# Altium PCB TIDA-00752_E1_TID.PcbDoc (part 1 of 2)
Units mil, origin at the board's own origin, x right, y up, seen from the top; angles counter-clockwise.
Board outline 600 x 3728.74 mil, 4 copper layers (Top Layer, GND, PWR, Bottom Layer), stack 62.2 mil thick; 88 components, 42 nets, 233 pads, 115 vias.
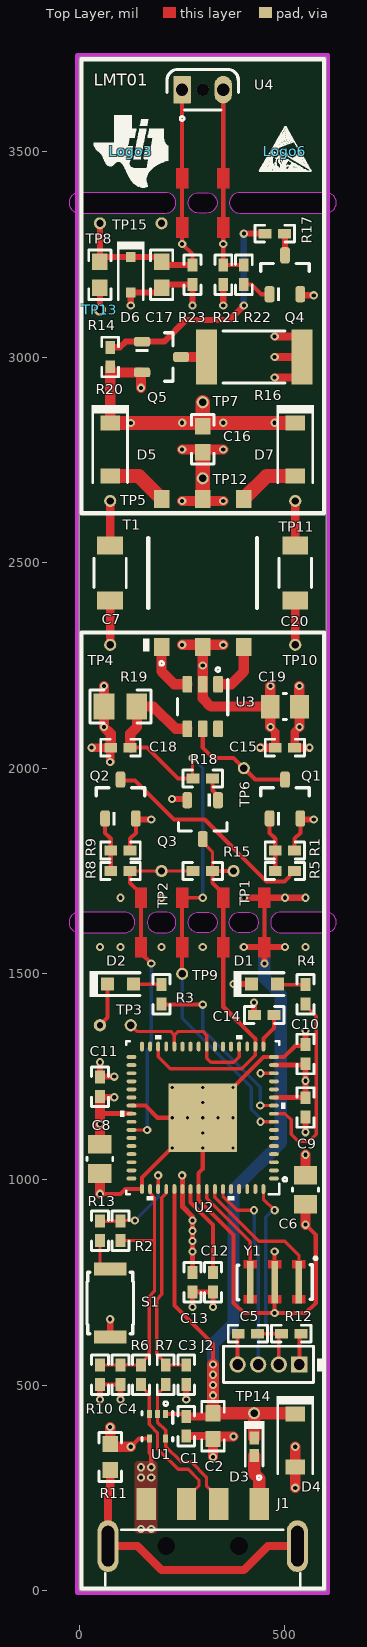
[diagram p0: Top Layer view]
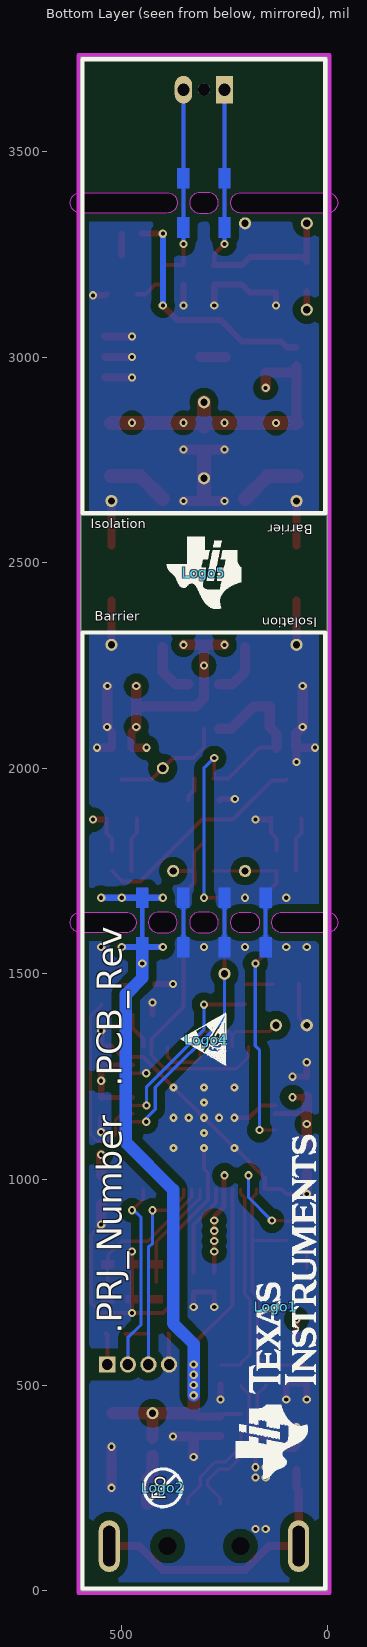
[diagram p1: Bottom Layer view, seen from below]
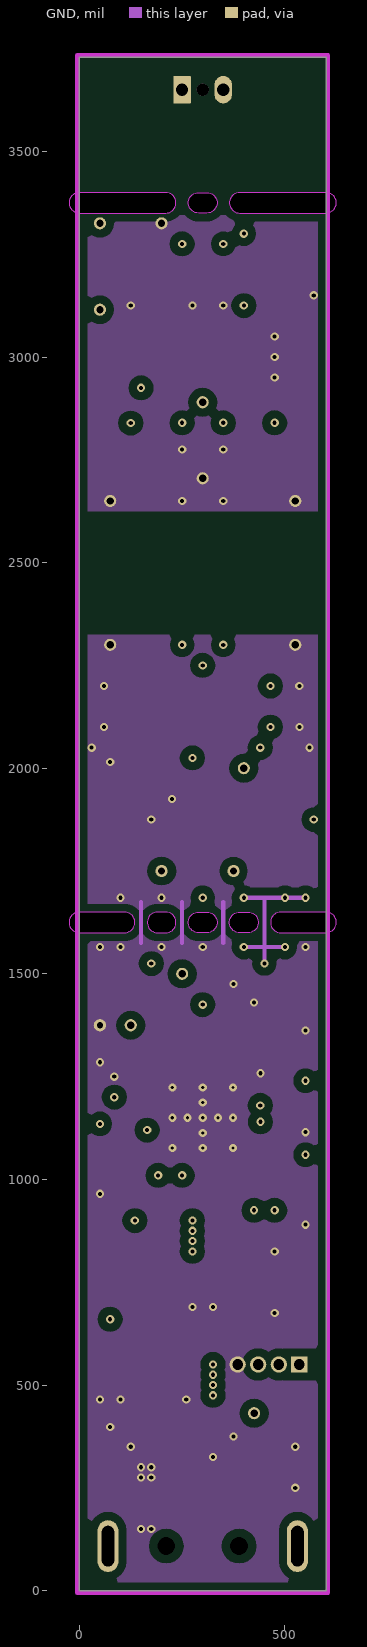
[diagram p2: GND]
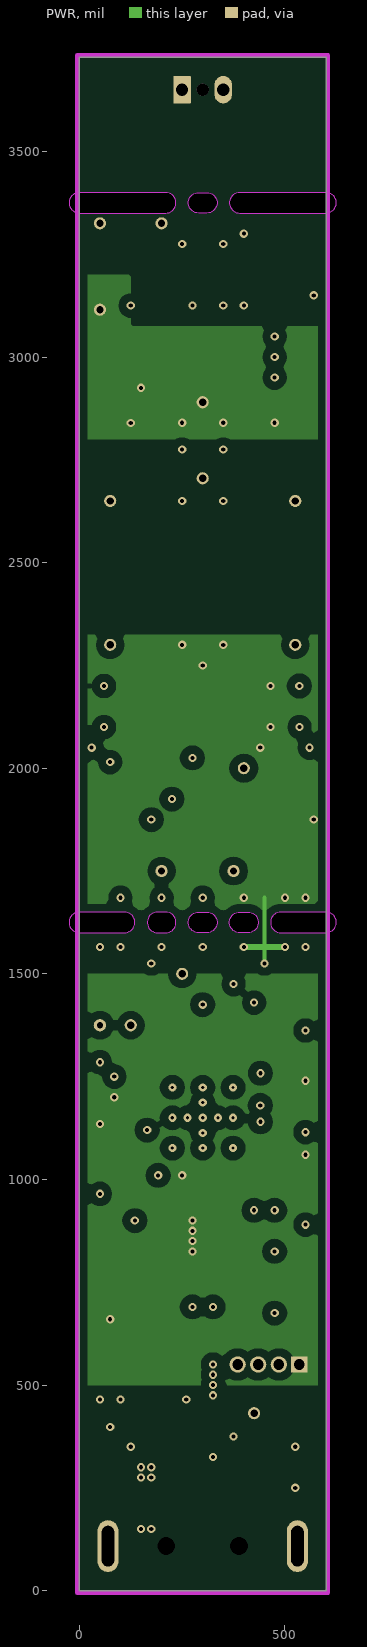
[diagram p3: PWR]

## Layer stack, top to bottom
Top Solder: solder mask 0.4, Solder Resist, Dk 3.5
Top Layer: signal copper 1.4
Dielectric 1: core 25.8, FR-4, Dk 4.2
GND: signal copper 1.4
Dielectric 2: prepreg 5, Dk 4.2
PWR: signal copper 1.4
Dielectric 3: core 25.8, FR-4, Dk 4.2
Bottom Layer: signal copper 1.4
Bottom Solder: solder mask 0.4, Solder Resist, Dk 3.5

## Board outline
0,0 0,3728.74 600,3728.74 600,0
cut-out: 0,3350 210,3350 ccw(c210,3375) 210,3400 0,3400 ccw(c0,3375)
cut-out: 290,3350 cw(c290,3375) 290,3400 310,3400 cw(c310,3375) 310,3350
cut-out: 390,3350 600,3350 ccw(c600,3375) 600,3400 390,3400 ccw(c390,3375)
cut-out: 0,1600 110,1600 ccw(c110,1625) 110,1650 0,1650 ccw(c0,1625)
cut-out: 190,1600 210,1600 ccw(c210,1625) 210,1650 190,1650 ccw(c190,1625)
cut-out: 290,1600 cw(c290,1625) 290,1650 310,1650 cw(c310,1625) 310,1600
cut-out: 390,1600 cw(c390,1625) 390,1650 410,1650 cw(c410,1625) 410,1600
cut-out: 490,1600 600,1600 ccw(c600,1625) 600,1650 490,1650 ccw(c490,1625)

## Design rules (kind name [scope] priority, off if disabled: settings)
AcuteAngle [All] p1: minimum=4.50000000000000E+0001 checktracksonly=FALSE
AssemblyTestPointUsage [All] p1: valid=2
Clearance Clearance_smd [IsSMTPin vs isvia] p1: gap=7.87
Clearance Clearance_BoardEdge_MountingHoles [OnCopper and InComponentClass('Mounting Holes') vs IsKeepOut] p2: gap=20
Clearance Clearance_BoardEdge_Poly [OnCopper and InPoly vs IsKeepOut] p3: gap=20
Clearance Clearance_BoardEdge [OnCopper and Not InComponentClass('Logo') and not InComponentClass('FiducialMark') and not InRegion(1000,500,4000,800) and Not IsKeepout vs IsKeepOut] p4: gap=20
Clearance Clearance_Poly [InPolygon] p5: gap=20
Clearance [All] p6: gap=7.87
ComponentClearance ComponentClearance_MountingHoles_FiducialMarks [InComponentClass('Mounting Holes') vs InComponentClass('FiducialMark')] p1: gap=50 collisioncheckmode=3 verticalgap=10 showdistances=FALSE
ComponentClearance ComponentClearance_Shunt [InComponentClass('Header') vs InComponentClass('Shunt')] p2: gap=0 collisioncheckmode=3 verticalgap=0 showdistances=FALSE
ComponentClearance ComponentClearance_Logo [InComponentClass('Logo')] p3: gap=50 collisioncheckmode=3 verticalgap=10 showdistances=FALSE
ComponentClearance ComponentClearance_ScrewToNut [(HasFootprint('NY PMS 440 0025 PH')) vs (HasFootprint('Keystone_1902C'))] p4: gap=5 collisioncheckmode=3 verticalgap=10 showdistances=FALSE
ComponentClearance ComponentClearance_MountingHoles [InComponentClass('Mounting Holes')] p5: gap=250 collisioncheckmode=3 verticalgap=100000 showdistances=FALSE
ComponentClearance ComponentClearance_SmallPassives [HasFootprint('0201*') or HasFootprint('0402*') or HasFootprint('0508') or HasFootprint('0603*') or HasFootprint('0612') or HasFootprint('0805*') or HasFootprint('0815*') or HasFootprint('0830*') or HasFootprint('1206*') or HasFootprint('1210*') or HasFootprint('1808*') or HasFootprint('1812*') or HasFootprint('1825*') or HasFootprint('2010*') or HasFootprint('2220*') or HasFootprint('2225*') or HasFootprint('2512*') or HasFootprint('2728*') or HasFootprint('3518*') vs HasFootprint('0201*') or HasFootprint('0402*') or HasFootprint('0508') or HasFootprint('0603*') or HasFootprint('0612') or HasFootprint('0805*') or HasFootprint('0815*') or HasFootprint('0830*') or HasFootprint('1206*') or HasFootprint('1210*') or HasFootprint('1808*') or HasFootprint('1812*') or HasFootprint('1825*') or HasFootprint('2010*') or HasFootprint('2220*') or HasFootprint('2225*') or HasFootprint('2512*') or HasFootprint('2728*') or HasFootprint('3518*')] p6: gap=15 collisioncheckmode=3 verticalgap=10 showdistances=FALSE
ComponentClearance ComponentClearance_THtoSMT [IsThruComponent vs IsSMTComponent] p7: gap=10 collisioncheckmode=3 verticalgap=30 showdistances=FALSE
ComponentClearance ComponentClearance_THtoTH [IsThruComponent vs IsThruComponent] p8: gap=30 collisioncheckmode=3 verticalgap=30 showdistances=FALSE
ComponentClearance [All] p9: gap=10 collisioncheckmode=3 verticalgap=10 showdistances=FALSE
DiffPairsRouting [All] p1: maxlimit=100 minlimit=8 mostfreqgap=10 toplayer_maxgap=15 toplayer_minwidth=8 toplayer_maxwidth=15 toplayer_prefwidth=10 midlayer1_mingap=10 midlayer1_minwidth=15 midlayer1_maxwidth=15 midlayer1_prefwidth=15 midlayer2_mingap=10 midlayer2_minwidth=15 midlayer2_maxwidth=15 midlayer2_prefwidth=15 bottomlayer_maxgap=15 bottomlayer_minwidth=8 bottomlayer_maxwidth=15 bottomlayer_prefwidth=10 maxuncoupledlength=1000
FabricationTestPointUsage TestPointUsage [All] p1: valid=2 allowmultiple=FALSE
FabricationTestpoint Testpoint [All] p1: side=3 testpointundercomponent=TRUE minsize=40 maxsize=100 preferedsize=60 minholesize=0 maxholesize=40 preferedholesize=32 testpointgrid=1 allowsidetop=TRUE allowsidebottom=TRUE usegrid=TRUE gridtolerance=0.01
FanoutControl Fanout_LCC [IsLCC] p1: bgadir=Out bgaviamode=Centered fanoutstyle=Auto fanoutdirection=Alternating viagrid=1 // Fanout_LCC (Default Rule)
FanoutControl Fanout_BGA [IsBGA] p2: bgadir=Out bgaviamode=Centered fanoutstyle=Auto fanoutdirection=Alternating viagrid=1 // Fanout_BGA (Default Rule)
FanoutControl Fanout_Default [All] p4: bgadir=Out bgaviamode=Centered fanoutstyle=Auto fanoutdirection=Alternating viagrid=1 // Fanout_Default (Default Rule)
FanoutControl Fanout_Small [(CompPinCount < 5)] p5: bgadir=Out bgaviamode=Centered fanoutstyle=Auto fanoutdirection=OutThenIn viagrid=1 // Fanout_Small (Default Rule)
HoleSize [All] p1: absolutevalues=TRUE maxlimit=251 minlimit=7.87 maxpercent=80.000 minpercent=20.000
MinimumAnnularRing MinimumAnnularRing_ThermalPadVias [IsVia and InAnyComponent] p1: minimumring=5
MinimumAnnularRing [All] p2: minimumring=5
MinimumSolderMaskSliver MinimumSolderMaskSliver_Logo [InComponentClass('Logo') vs InComponentClass('Logo')] p1: minsoldermaskwidth=0.7
MinimumSolderMaskSliver [All] p2: minsoldermaskwidth=3.94
PlaneConnect [All] p1: planeconnectstyle=Direct reliefexpansion=10 reliefentries=4 reliefconductorwidth=10 reliefairgap=10
PolygonConnect [All] p1: connectstyle=Direct reliefconductorwidth=10 reliefentries=4 polygonreliefangle="90 Angle" airgapwidth=10
RoutingVias ThermalPadVias [IsVia and InAnyComponent] p1: holewidth=7.87 width=19.68 viastyle="Through Hole" minholewidth=7.87 minwidth=19.68 maxholewidth=12.99 maxwidth=23.62
RoutingVias [All] p2: holewidth=10 width=20 viastyle="Through Hole" minholewidth=7.87 minwidth=16 maxholewidth=40 maxwidth=65
SilkToBoardRegionClearance [Not ((IsComment or IsDesignator) And (Hide <> 'False')) and not InRegion(1000,500,4000,800)] p1:
SilkToSilkClearance SilkToSilkClearance_Pb-FreeLogo [(HasFootprint('Pb-Free_Overlay_Medium') OR HasFootprint('Pb-Free_Overlay_Small')) vs (HasFootprint('Pb-Free_Overlay_Medium') OR HasFootprint('Pb-Free_Overlay_Small'))] p1: silktosilkclearance=5
SilkToSilkClearance [All] p2: silktosilkclearance=5
SilkToSolderMaskClearance SilkToComonentPadClearance [IsPad and InAnycomponent] p1: minsilkscreentomaskgap=5 clearancetoexposedcopper=TRUE
SilkToSolderMaskClearance "Silk to Solder Mask Opening" [All] p2: minsilkscreentomaskgap=5 clearancetoexposedcopper=FALSE
SolderMaskExpansion [All] p1: expansion=1.97
UnpouredPolygon [All] p1: allowunpoured=FALSE
Width [All] p1: maxlimit=100 minlimit=8 preferedwidth=10 checkconnectedcopper=TRUE
14 further rules are at their usual default settings.

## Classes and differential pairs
component class Header: J2
component class TIDA-00752_E1_MSP430_LMT01: C1 C2 C3 C4 C5 C6 C7 C8 C9 C10 C11 C12 C13 C14 C15 C16 C17 C18 C19 C20 D1 D2 D3 D4 D5 D6 D7 J1 J2 Q1 Q2 Q3 Q4 Q5 R1 R2 R3 R4 R5 R6 R7 R8 R9 R10 R11 R12 R13 R14 R15 R16 R17 R18 R19 R20 R21 R22 R23 S1 T1 TP1 TP2 TP3 TP4 TP5 TP6 TP7 TP8 TP9 TP10 TP11 TP12 TP13 TP14 TP15 U1 U2 U3 U4 Y1
component class Logo: Logo1 Logo3 Logo5
component class TIDA-00752_E1_TID_Hardware: FID1 FID2 FID3 Logo1 Logo2 Logo3 Logo4 Logo5 Logo6 ZZ1 ZZ2 ZZ3
component class AssemblyNote: ZZ1 ZZ2 ZZ3

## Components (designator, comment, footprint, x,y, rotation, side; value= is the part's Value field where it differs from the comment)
C1 "C1005X7R1H104K050BB" 0402 260,400 r270 top
C2 "0603ZD475KAT2A" 0603 325,400 r270 top
C3 "500R07S100JV4T" 0402 260,525 r270 top
C4 "500R07S100JV4T" 0402 100,525 r270 top
C5 "GRM155R70J222KA01D" 0402 410,625 r180 top
C6 "C2012X7R1A106K125AC" 0805_145 550,975 r270 top
C7 "202R18W102KV4E" 1206_190 75,2475 r270 top
C8 "C2012X7R1A106K125AC" 0805_145 50,1050 r270 top
C9 "C1005X7R1H104K050BB" 0402 550,1175 r270 top
C10 "C1005X7R1H104K050BB" 0402 550,1305 r90 top
C11 "C1005X7R1H104K050BB" 0402 50,1225 r90 top
C12 "GRM155R61A224KE19D" 0402 325,750 r270 top
C13 "GRM155R61A224KE19D" 0402 275,750 r270 top
C14 "C1005X5R1A474K050BB" 0402 450,1400 r180 top
C15 "C1005X7R1H104K050BB" 0402 500,2050 r0 top
C16 "06033C104JAT2A" 0603 300,2800 r270 top
C17 "GRM188R71A105KA61D" 0603 200,3200 r270 top
C18 "GRM155R71C224KA12D" 0402 100,2050 r180 top
C19 "EMK212BB7106MG-T" 0805_145 500,2149.99 r0 top
C20 "202R18W102KV4E" 1206_190 525,2475 r270 top
D1 "150060VS75000" WL-SMCW_GREEN 450,1475 r0 top
D2 "150060SS75000" WL-SMCW_RED 100,1475 r0 top
D3 "SBR0220T5-7-F" SOD-523 425,350 r270 top
D4 "MMSZ5232B-7-F" SOD-123 525,365 r270 top
D5 "MBR0540T1G" SOD-123 75,2775 r270 top
D6 "D3Z5V1BF-7" SOD-323F 125,3200 r270 top
D7 "MBR0540T1G" SOD-123 525,2775 r270 top
J1 "48037-2200" CONN_USB_0480372200 300,0 r0 top
J2 "850-10-004-10-001101" Preci-dip_850-xx-004-10-001101 460,550 r180 top
Logo1 "Texas Instruments" TI_Stacked_Overlay_Small 125,690 r90 bottom
Logo2 "Pb-Free Symbol" Pb-Free_Overlay_Small 400,250 r90 bottom
Logo3 "Texas Instruments" TI_Symbol_Overlay_Small 125,3500 r0 top
Logo4 "ESD Susceptible" ESD_Overlay_Small 295,1340 r90 bottom
Logo5 "Texas Instruments" TI_Symbol_Overlay_Small 300,2475 r180 bottom
Logo6 "ESD Susceptible" ESD_Overlay_Small 500,3500 r0 top
Q1 "MMBT3906" SOT-23 500,1925 r90 top
Q2 "MMBT3904" SOT-23 100,1925 r90 top
Q3 "MMBT3904" SOT-23 300,1875 r270 top
Q4 "MMBT3904" SOT-23 500,3200 r90 top
Q5 "MMBT3906" SOT-23 200,3000 r0 top
R1 "CRCW040210K0FKED" 0402 500,1800 r180 top
R2 "ERJ-2RKF1401X" 0402 100,875 r90 top
R3 "CRCW04021K00JNED" 0402 200,1450 r90 top
R4 "CRCW04021K00JNED" 0402 550,1450 r90 top
R5 "CRCW04021K00JNED" 0402 500,1750 r180 top
R6 "CRCW040227R0JNED" 0402 150,525 r90 top
R7 "CRCW040227R0JNED" 0402 210,525 r90 top
R8 "CRCW04022K00JNED" 0402 100,1750 r180 top
R9 "CRCW04021K00JNED" 0402 100,1800 r180 top
R10 "CRCW04021M00JNED" 0402 50,525 r90 top
R11 "CRCW060333R0FKEA" 0603 75,325 r270 top
R12 "CRCW040233K0JNED" 0402 515,625 r180 top
R13 "ERJ-2RKF1000X" 0402 50,875 r270 top
R14 "RC0603JR-07560RL" 0603 50,3200 r90 top
R15 "CRCW04024K70JNED" 0402 300,1750 r180 top
R16 "CRCW2512249RFKEG" 2512 425,3000 r180 top
R17 "CRCW040211K0JNED" 0402 475,3300 r180 top
R18 "CRCW040210K0FKED" 0402 300,1975 r180 top
R19 "RC0805FR-0710RL" 0805_HV 100,2150 r0 top
R20 "CRCW0402110KJNED" 0402 75,3000 r270 top
R21 "CRCW040210K0FKED" 0402 350,3200 r270 top
R22 "CRCW040222K0JNED" 0402 400,3200 r90 top
R23 "CRCW04025K10JNED" 0402 275,3200 r90 top
S1 "SKRKAEE010" SW_SKRKAEE010 75,700 r270 top
T1 "760390014" Wurth_760390013 300,2475 r90 top
TP1 "TESTPOINT" TP_H045P075 375,1750 r90 top
TP2 "TESTPOINT" TP_H045P075 200,1750 r90 top
TP3 "TESTPOINT" TP_H045P075 125,1375 r90 top
TP4 "TESTPOINT" TP_H045P075 75,2300 r90 top
TP5 "TESTPOINT" TP_H045P075 75,2650 r90 top
TP6 "TESTPOINT" TP_H045P075 400,2000 r90 top
TP7 "TESTPOINT" TP_H045P075 300,2890 r90 top
TP8 "TESTPOINT" TP_H045P075 50,3325 r90 top
TP9 "TESTPOINT" TP_H045P075 250,1500 r90 top
TP10 "TESTPOINT" TP_H045P075 525,2300 r90 top
TP11 "TESTPOINT" TP_H045P075 525,2650 r90 top
TP12 "TESTPOINT" TP_H045P075 300,2705 r90 top
TP13 "TESTPOINT" TP_H045P075 50,3115 r90 top
TP14 "TESTPOINT" TP_H045P075 425,431.5 r90 top
TP15 "TESTPOINT" TP_H045P075 200,3325 r90 top
U1 "TPD2E001DRLR" DRL0005A 190,400 r270 top
U2 "MSP430F5528IRGC" RGC0064B 300,1150 r180 top
U3 "SN6505BDBVR" DBV0006A_N 300,2150 r270 top
U4 "LMT01LPG" LPG0002A 300,3650 r0 top
Y1 "CSTCR4M00G15L99-R0" Murata_CSTCR 475,750 r180 top
ZZ1 "These assemblies are ESD sensitive, ESD precautions shall be observed." AssemblyNote 0,4975 r0 top
ZZ2 "These assemblies must be clean and free from flux and all contaminants. Use of no clean flux is not acceptable." AssemblyNote 0,4825 r0 top
ZZ3 "These assemblies must comply with workmanship standards IPC-A-610 Class 2, unless otherwise specified." AssemblyNote 0,4675 r0 top

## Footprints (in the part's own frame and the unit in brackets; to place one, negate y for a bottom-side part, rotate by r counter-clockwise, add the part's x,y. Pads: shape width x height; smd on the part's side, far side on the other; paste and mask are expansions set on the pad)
0402 [mm] "0402 from SM-752 data"
  rect 0.8x0.6 smd: 1(-0.6,0) 2(0.6,0)
  silkscreen extent -1.22,-0.52 1.22,0.52, body extent -0.55,-0.3 0.55,0.3, height 0.6
0603 [mm] "0603 from SM-752 data"
  rect 1x0.95 smd: 1(-0.8,0) 2(0.8,0)
  silkscreen extent -1.52,-0.69 1.52,0.69, body extent -0.87,-0.47 0.87,0.47, height 1
0805_145 [mm] "0805 / 1.45mm height"
  rect 1.15x1.45 smd: 1(-0.9,0) 2(0.9,0)
  silkscreen extent -0.1,-0.8 0.1,0.8, body extent -1.1,-0.72 1.1,0.72, height 1.45
0805_HV [mil] "0805 with 30mil clearance between pads"
  rect 50x63 smd: 1(-40,0) 2(40,0)
  silkscreen extent -74,-40 74,40, body extent -43,-29 43,29, height 57
1206_190 [mm] "1206_190"
  rect 1.1x1.6 smd: 1(-1.7,0) 2(1.7,0)
  silkscreen extent -0.9,-1 0.9,1, body extent -1.75,-0.95 1.75,0.95, height 1.9
2512 [mm] "Chip Resistor, Body 6.3x3.2mm, IPC Medium Density"
  rect 1.3x3.4 smd: 1(-2.95,0) 2(2.95,0)
  silkscreen extent -1.9,-1.6 1.9,1.6, body extent -3.22,-1.67 3.22,1.67, height 0.71
AssemblyNote [mil] "Assembly Note"
CONN_USB_0480372200 [mm] "MOLEX"
  rect 1.2x2 smd: 1(3.5,5.35) 2(1,5.35) 3(-1,5.35) 4(-3.5,5.35)
  oval 1.3x3.2 hole 0.762 slot 2.5 at 90 deg mask+0.064: 5(5.85,2.75) 6(-5.85,2.75)
  round 1 hole 1.1 unplated mask+0.254: 7(-2.25,2.75) 8(2.25,2.75)
  body extent -6.02,-15 6.03,5.95, height 2.25
DBV0006A_N [mm] "SOT23, 6-Leads, Body 2.9x1.6mm, Pitch 0.95mm, Lead Span 2.8mm, IPC Medium Density"
  rrect17% 1x0.6 smd: 1(-1.375,0.95) 2(-1.375,0) 3(-1.375,-0.95) 4(1.375,-0.95) 5(1.375,0) 6(1.375,0.95)
  silkscreen extent -1.68,-1.55 0.5,1.55, body extent -1.42,-1.46 1.42,1.46, height 1.12
DRL0005A [mm] "SOTFL, 5-Flat Leads, Body 1.2x1.6x0.6mm, Pitch 0.5mm, TI recommended"
  rect 0.5x0.3 smd: 1(-0.75,0.5) 2(-0.75,0) 3(-0.75,-0.5) 4(0.75,-0.5) 5(0.75,0.5)
  silkscreen extent -0.9,-0.95 0.9,0.95, body extent -0.85,-0.85 0.85,0.85, height 0.62
ESD_Overlay_Small [mil]
  silkscreen extent -62,-48 64,61
LPG0002A [mm] "TO, 2-Leads, Body 4x1.52mm"
  rrect9% 1.07x1.7 hole 0.75 mask+0.064: 1(-1.27,0)
  rrect100% 1.07x1.7 hole 0.75 mask+0.064: 2(1.27,0)
  round 0.75 hole 0.75 unplated paste+0 mask+0.127: MH(0,0)
  silkscreen extent -2.21,-1.25 2.21,1.25, body extent -2,-0.54 2,0.98, height 5.06
Murata_CSTCR [mm] "Murata"
  rect 0.4x2.6 smd mask+0.051: 1(-1.5,0) 2(0,0) 3(1.5,0)
  Top Layer region: -1.9,-1.35 -1.9,-0.85 -1.1,-0.85 -1.1,-1.35
  Top Layer region: -0.4,-1.35 -0.4,-0.85 0.4,-0.85 0.4,-1.35
  Top Layer region: -0.4,-1.35 -0.4,-0.85 0.4,-0.85 0.4,-1.35
  Top Layer region: -1.9,-1.35 -1.9,-0.85 -1.1,-0.85 -1.1,-1.35
  Top Layer region: -1.9,0.8 -1.1,0.8 -1.1,1.3 -1.9,1.3
  Top Layer region: -0.4,0.8 0.4,0.8 0.4,1.3 -0.4,1.3
  Top Layer region: 1.1,-1.35 1.1,-0.85 1.9,-0.85 1.9,-1.35
  Top Layer region: 1.1,-1.35 1.1,-0.85 1.9,-0.85 1.9,-1.35
  Top Layer region: 1.1,0.8 1.9,0.8 1.9,1.3 1.1,1.3
  silkscreen extent -2.61,-1.56 2.32,1.08, body extent -2.3,-1.05 2.3,1.05, height 1.2
Pb-Free_Overlay_Small [mil]
  silkscreen extent -46,-46 46,46
Preci-dip_850-xx-004-10-001101 [mm] "Preci-dip"
  rect 1x1 hole 0.65 mask+0.064: 1(-1.905,0)
  round 1 hole 0.65 mask+0.064: 2(-0.635,0) 3(0.635,0) 4(1.905,0)
  silkscreen extent -3.32,-1.12 2.78,1.12, body extent -2.74,-1.1 2.74,1.1, height 5.2
RGC0064B [mm]
  oval 0.6x0.24 smd mask+0.07: 1(-4.4,3.75) 2(-4.4,3.25) 3(-4.4,2.75) 4(-4.4,2.25) 5(-4.4,1.75) 6(-4.4,1.25) 7(-4.4,0.75) 8(-4.4,0.25) 9(-4.4,-0.25) 10(-4.4,-0.75) 11(-4.4,-1.25) 12(-4.4,-1.75) 13(-4.4,-2.25) 14(-4.4,-2.75) 15(-4.4,-3.25) 16(-4.4,-3.75) 33(4.4,-3.75) 34(4.4,-3.25) 35(4.4,-2.75) 36(4.4,-2.25) 37(4.4,-1.75) 38(4.4,-1.25) 39(4.4,-0.75) 40(4.4,-0.25) 41(4.4,0.25) 42(4.4,0.75) 43(4.4,1.25) 44(4.4,1.75) 45(4.4,2.25) 46(4.4,2.75) 47(4.4,3.25) 48(4.4,3.75)
  oval 0.24x0.6 smd mask+0.07: 17(-3.751,-4.4) 18(-3.251,-4.4) 19(-2.751,-4.4) 20(-2.251,-4.4) 21(-1.75,-4.4) 22(-1.25,-4.4) 23(-0.75,-4.4) 24(-0.25,-4.4) 25(0.25,-4.4) 26(0.75,-4.4) 27(1.25,-4.4) 28(1.75,-4.4) 29(2.251,-4.4) 30(2.751,-4.4) 31(3.251,-4.4) 32(3.751,-4.4) 49(3.751,4.4) 50(3.251,4.4) 51(2.751,4.4) 52(2.251,4.4) 53(1.75,4.4) 54(1.25,4.4) 55(0.75,4.4) 56(0.25,4.4) 57(-0.25,4.4) 58(-0.75,4.4) 59(-1.25,4.4) 60(-1.75,4.4) 61(-2.251,4.4) 62(-2.751,4.4) 63(-3.251,4.4) 64(-3.751,4.4)
  rect 4.25x4.25 smd paste-2.112: 65(0,0)
  silkscreen extent -5.1,-5.1 5.1,5.1, body extent -4.57,-4.57 4.57,4.57, height 1.01
SOD-123 [mm] "On Semi recommended land pattern"
  rect 0.915x1.22 smd: 1(-1.637,0) 2(1.637,0)
  silkscreen extent -2.74,-1.17 2.03,1.17, body extent -1.93,-0.9 1.93,0.9, height 1.35
SOD-323F [mm] "NXP recommended land pattern"
  rect 0.6x0.6 smd paste-0.05: 1(-1.1,0) 2(1.1,0)
  silkscreen extent -2.06,-0.86 1.53,0.86, body extent -1.35,-0.67 1.35,0.68, height 0.79
SOD-523 [mm] "NXP Semiconductor recommended land pattern, nominal STEP model"
  rect 0.8x0.6 smd paste-0.05: 1(-0.55,0) 2(0.55,0)
  silkscreen extent -1.6,-0.64 1.2,0.63, body extent -0.8,-0.4 0.8,0.4, height 0.72
SOT-23 [mm] "SOT23, 3-Leads, Body 2.9x1.3mm, Pitch 0.95mm, Lead Span 2.5mm, IPC Medium Density"
  rrect50% 1x0.6 smd: 1(-1.2,0.95) 2(-1.2,-0.95) 3(1.2,0)
  silkscreen extent -1.62,-1.5 0.7,1.5, body extent -1.16,-1.45 1.21,1.45, height 1
SW_SKRKAEE010 [mm] "Alps recommended land pattern"
  rect 0.8x2 smd: 1(-2.1,0) 2(2.1,0)
  silkscreen extent -1.9,-1.44 1.92,1.44, body extent -2.4,-1.45 2.4,1.45, height 1.96
TI_Stacked_Overlay_Small [mil]
  silkscreen extent -418,-98 418,98
TI_Symbol_Overlay_Small [mil]
  silkscreen extent -90,-88 91,88
TP_H045P075 [mm] "TP_H0.45P0.75"
  round 0.75 hole 0.45: 1(0,0)
WL-SMCW_GREEN [mm] "WURTH"
  rect 0.8x0.8 smd: 1(-0.8,0) 2(0.8,0)
  silkscreen extent -1.9,-0.8 1.2,0.8, body extent -0.85,-0.45 0.85,0.45, height 0.8
WL-SMCW_RED [mm] "WURTH"
  rect 0.8x0.8 smd: 1(-0.8,0) 2(0.8,0)
  silkscreen extent -1.9,-0.8 1.2,0.8, body extent -0.85,-0.45 0.85,0.45, height 0.8
Wurth_760390013 [mil] "Wurth"
  rect 44x38 smd: 1(-180,100) 2(-180,0) 3(-180,-100) 4(180,-100) 5(180,0) 6(180,100)
  silkscreen extent -190,-132 85,145, body extent -198,-135 198,130, height 166

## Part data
C1 C9 C10 C11 C15: "CAP, CERM, 0.1 µF, 50 V, +/- 10%, X7R, 0402"
C2: "CAP, CERM, 4.7 µF, 10 V, +/- 10%, X5R, 0603"
C3 C4: "CAP, CERM, 10 pF, 50 V, +/- 5%, C0G/NP0, 0402"
C5: "CAP, CERM, 2200pF, 6.3V, +/-10%, X7R, 0402"
C6 C8: "CAP, CERM, 10 µF, 10 V, +/- 10%, X7R, 0805"
C7 C20: "CAP, CERM, 1000 pF, 2000 V, +/- 10%, X7R, 1206_190"
C12 C13: "CAP, CERM, 0.22 µF, 10 V, +/- 10%, X5R, 0402"
C14: "CAP, CERM, 0.47 µF, 10 V, +/- 10%, X5R, 0402"
C16: "CAP, CERM, 0.1 µF, 25 V, +/- 5%, X7R, 0603"
C17: "CAP, CERM, 1 µF, 10 V, +/- 10%, X7R, 0603"
C18: "CAP, CERM, 0.22 µF, 16 V, +/- 10%, X7R, 0402"
C19: "CAP, CERM, 10 µF, 16 V, +/- 20%, X7R, 0805"
D1: "LED, Green, SMD"
D2: "LED, Super Red, SMD"
D3: "Diode, Schottky, 20 V, 0.2 A, SOD-523"
D4: "Diode, Zener, 5.6V, 500mW, SOD-123"
D5 D7: "Diode, Schottky, 40 V, 0.5 A, SOD-123"
D6: "Diode, Zener, 5.1 V, 400 mW, SOD-323F"
J1: "Connector, Plug, USB Type A, R/A, Top Mount SMT"
J2: "Header, 50mil, 4x1, Gold, TH"
Logo1 Logo3 Logo5: library part TI_Logo, "Texas Instrument Corporate Signature"
Logo2: library part Pb-Free
Logo4 Logo6: library part ESD_Susceptible, "ESD Susceptible Symbol"
Q1 Q5: library part "MMBT3906, Fairchild Semiconductor", "Transistor, PNP, 40 V, 0.2 A, SOT-23"
Q2 Q3 Q4: library part "MMBT3904, Fairchild Semiconductor", "Transistor, NPN, 40 V, 0.2 A, SOT-23"
R1 R18 R21: "RES, 10.0 k, 1%, 0.063 W, 0402"
R2: "RES, 1.40 k, 1%, 0.1 W, 0402"
R3 R4: "RES, 1.0k ohm, 5%, 0.063W, 0402"
R5 R9: "RES, 1.0 k, 5%, 0.063 W, 0402"
R6 R7: "RES, 27, 5%, 0.063 W, 0402"
R8: "RES, 2.0 k, 5%, 0.063 W, 0402"
R10: library part CRCW040233K0JNED, "RES,1M ohm, 5%, 0.063W, 0402"
R11: "RES, 33.0, 1%, 0.1 W, 0603"
R12: "RES, 33k ohm, 5%, 0.063W, 0402"
R13: "RES, 100, 1%, 0.1 W, 0402"
R14: "RES, 560, 5%, 0.1 W, 0603"
R15: "RES, 4.7 k, 5%, 0.063 W, 0402"
R16: "RES, 249, 1%, 1 W, 2512"
R17: "RES, 11 k, 5%, 0.063 W, 0402"
R19: "RES, 10.0, 1%, 0.125 W, 0805"
R20: "RES, 110 k, 5%, 0.063 W, 0402"
R22: "RES, 22 k, 5%, 0.063 W, 0402"
R23: "RES, 5.1 k, 5%, 0.063 W, 0402"
S1: "Switch, Push Button, SMD"
T1: "Transformer, 475uH, SMT"
TP1 TP2 TP3 TP4 TP5 TP6 TP7 TP8 TP9 TP10 TP11 TP12 TP13 TP14 TP15: library part TP_H0.45P0.75, "Testpoint"
U1: "Low-Capacitance + / - 15 kV ESD-Protection Array for High-Speed Data Interfaces, 2 Channels, -40 to +85 degC, 5-pin SOT (DRL), Green (RoHS & no Sb/Br)"
U2: "Mixed Signal MicroController, RGC0064B"
U3: "LOW-NOISE 1A TRANSFORMER DRIVERS FOR ISOLATED POWER SUPPLIES, DBV0006A"
U4: "0.5°C Accurate 2-Pin Digital NTC or PTC Thermistor Replacement, LPG0002A"
Y1: "Resonator, 4MHz, 39pF SMD"
ZZ1 ZZ2 ZZ3: library part AssemblyNote

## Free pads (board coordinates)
  round 30 hole 15: 0(50,1375)

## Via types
v1: diameter 20, hole 10, Top Layer to Bottom Layer, tented both sides, 102 vias
v2: diameter 19.68, hole 7.87, Top Layer to Bottom Layer, tented both sides, 13 vias

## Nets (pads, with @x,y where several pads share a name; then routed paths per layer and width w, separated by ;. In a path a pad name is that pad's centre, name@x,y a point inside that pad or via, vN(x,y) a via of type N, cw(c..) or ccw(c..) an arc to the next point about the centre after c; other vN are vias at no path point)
COMP_MODE: TP3.1 U2.20 U2.24 U2.28 | length 398.7
  Top Layer w8: TP3.1@125,1375 140,1360 222.16,1360 231.08,1351.08 ; U2.28@231.08,1323.23 231.08,1351.08 ; U2.20@388.6,1323.23 388.6,1298.6 375,1285 320,1285 309.84,1295.16 U2.24@309.84,1323.23 309.84,1349.84 310,1350 300,1360 240,1360 231.08,1351.08
DATA_OUT: C18.1 R18.2 R19.2 TP9.1 U2.8 U3.4 | length 1543
  Top Layer w8: 250,1685 v1(300,1685) ; v1(275,2025) 275,1976.38 R18.2@276.38,1975 ; v1(440.47,1140.16) U2.8@473.23,1140.16
  Top Layer w10: C18.1@123.62,2050 165,2050 240,1975 R18.2@276.38,1975 ; TP9.1@250,1500 250,1685
  Top Layer w25: C18.1@123.62,2050 123.62,2083.62 140,2100 R19.2@140,2150 180,2150 234.14,2095.86 U3.4@262.6,2095.86
  Bottom Layer w8: TP9.1@250,1500 250,1391.93 418.13,1223.81 418.13,1170.94 440.47,1148.6 v1(440.47,1140.16) ; v1(275,2025) 300,2000 v1(300,1685)
DATA_OUT_NOT: Q3.3 R15.1 TP1.1 U2.18 U2.30 | length 907.1
  Top Layer w8: U2.30@191.7,1323.23 191.7,1298.3 220.87,1269.13 395.26,1269.13 427.98,1301.85 U2.18@427.98,1323.23 ; Q3.3@300,1827.76 300,1820 323.62,1796.38 R15.1@323.62,1750
  Top Layer w10: 350,1685 350,1420 427.98,1342.02 U2.18@427.98,1323.23 ; 350,1695 323.62,1721.38 R15.1@323.62,1750 TP1.1@375,1750
DM_USB: J1.2 R7.1 U1.2 U1.5 | length 375.4
  Top Layer w8: U1.5@209.69,370.47 210,370.79 210,390 190,410 U1.2@190,429.53 190,477.44 210,497.44 R7.1@210,501.38 ; U1.5@210,370.47 210,350.46 247.46,313 272,313 309,276 309,255 339.37,224.63 J1.2@339.37,210.63
DP_USB: J1.3 R6.1 U1.3 | length 376.1
  Top Layer w8: R6.1@150,501.38 150,497.5 170.32,477.19 U1.3@170.32,429.53 170.32,404.68 172,403 172,402.54 190,384.54 190,345 240,295 264.54,295 291,268.54 291,255 260.63,224.63 J1.3@260.63,210.63
EN_PWR: R8.1 R15.2 TP2.1 U2.42 | length 836.6
  Top Layer w8: R8.1@123.62,1750 R15.2@276.38,1750 ; U2.42@126.77,1120.48 127.24,1120 v1(165,1120)
  Top Layer w10: R8.1@123.62,1750 123.62,1721.38 150,1695 ; 150,1685 150,1550 v1(175,1525)
  Bottom Layer w8: v1(165,1120) 165,1315 175,1325 v1(175,1525)
EN_SN6505: Q1.3 TP6.1 U3.5 | length 278.1
  Top Layer w10: U3.5@300,2095.86 300,2050 325,2025 375,2025 427.76,1972.24 Q1.3@500,1972.24
GLED: R4.1 U2.9 | length 485
  Top Layer w8: U2.9@473.23,1159.85 500.15,1159.85 515,1145 515,1110 531.87,1093.13 559.06,1093.13 576,1110.07 576,1396.5 550,1422.5 R4.1@550,1426.38
GND: C1.2 C2.2 C3.2 C4.2 C5.2 C6.2 C7.2 C8.2 C9.2 C10.2 C11.2 C12.2 C13.2 C14.2 C15.2 C18.2 C19.2 C20.2 D1.1 D2.1 D4.2 J1.4 J2.4 pad.0 Q2.2 Q3.2 R9.1 R10.1 R11.1 R19.1 TP4.1 TP10.1 U1.4 U2.14 U2.16 U2.39 U2.49 U2.56 U2.65 Y1.2 | length 4547.6
  Top Layer w8: U2.39@126.77,1179.53 149.99,1179.53 ; U2.56@290.15,976.78 290.15,1000 ; v1(440.47,1258.27) U2.14@473.23,1258.27
  Top Layer w10: R10.1@50,501.38 C4.2@100,501.38 ; v1(50,965) 100,965 111.78,976.78 U2.49@152.32,976.78 152.32,1004.67 223.84,1076.18 v2(226.18,1076.18) v2(300,1150) v2(373.82,1223.82) 447.63,1297.64 U2.16@473.23,1297.64 497.64,1297.64 525,1325 C10.2@550,1325 ; pad.0@50,1375 68.5,1393.5 D2.1@68.5,1475 ; R11.1@75,356.5 R11.1@81.5,350 ; R9.1@123.62,1800 123.62,1828.62 137.4,1842.4 Q2.2@137.4,1877.76 ; v1(125,350) 145.47,370.47 U1.4@170.32,370.47 170.32,335.32 175,330.63 v1(175,300) ; U2.39@126.77,1179.53 160.47,1179.53 190,1150 v2(226.18,1150) ; v2(300,1076.18) 300,1025 290.15,1015.15 U2.56@290.15,976.78 290.15,949.85 375,865 375,700 400,675 v1(475,675) ; J2.4@385,550 385,623.62 C5.2@386.38,625 ; v1(475,825) Y1.2@475,750 v1(475,675) ; v1(550,890) 575,865 575,700 550,675 v1(475,675)
  Top Layer w12: v1(275,690) C13.2@275,726.38 C12.2@325,726.38 v1(325,690)
  Top Layer w15: v1(50,465) R10.1@50,501.38 ; C11.2@50,1248.63 v1(50,1285) ; C11.2@50,1250 v1(85,1250) ; v1(100,465) C4.2@100,501.38 ; Q2.2@137.4,1877.76 140.16,1875 v1(175,1875) ; v1(225,1925) 259.84,1925 Q3.2@262.6,1922.24 ; v1(260,465) C3.2@260,501.38 ; v1(375,1475) D1.1@418.5,1475 ; C14.2@425,1401.38 v1(425,1430) ; v1(550,1115) C9.2@550,1148.62 ; C10.2@550,1328.62 v1(550,1362.24)
  Top Layer w20: v1(30,2050) C18.2@76.38,2050 ; v1(75,2015) C18.2@75,2048.62 ; TP4.1@75,2300 C7.2@75,2408.07 ; C1.2@260,376.38 C2.2@317.13,376.38 ; TP10.1@525,2300 C20.2@525,2408.07 ; v1(535.43,2099.99) 523.62,2088.18 C15.2@523.62,2050 550,2050
  Top Layer w25: v1(50,965) C8.2@50,1014.57 ; v1(60,2200) R19.1@60,2150 v1(60,2099.99) 76.38,2083.61 C18.2@76.38,2050 ; R11.1@75,356.5 v1(75,398.22) ; R11.1@81.5,350 v1(125,350) ; v1(325,325) C2.2@325,368.5 331.5,375 v1(375,375) ; D4.2@524.47,300 D4.2@525,300.53 ; v1(525,250) D4.2@525,300.53 ; v1(525,350) D4.2@525,300.53 ; C19.2@535,2150 v1(535,2200) ; v1(535.43,2099.99) C19.2@535.43,2149.99 ; v1(550,890) C6.2@550,939.57
  GND w10: 150,1575 150,1675 ; 250,1575 250,1675 ; 350,1575 350,1675
  Bottom Layer w10: 150,1565 150,1685 ; 250,1565 250,1685 ; 350,1565 350,1685
  other v1: 150,150 175,150 150,275 175,275 150,300 50,1565 100,1565 200,1565 300,1565 550,1565 100,1685 200,1685 560,2050
  other v2: 373.82,1076.18 300,1113.09 263.09,1150 336.91,1150 373.82,1150 300,1186.91 226.18,1223.82 300,1223.82
ISOGND: C7.1 C16.2 C17.2 C20.1 D6.2 Q4.2 R16.1 R21.2 R23.1 T1.5 TP5.1 TP11.1 TP12.1 TP15.1 | length 1052.5
  Top Layer w15: v1(125,3125) D6.2@125,3156.69 188.19,3156.69 C17.2@200,3168.5 207.87,3176.38 R23.1@275,3176.38 v1(275,3125) ; v1(350,3125) R21.2@350,3176.37 ; Q4.2@537.4,3152.76 540.16,3150 v1(570,3150)
  Top Layer w20: C7.1@75,2541.92 TP5.1@75,2650 ; v1(475,2950) R16.1@540,2950 ; v1(475,3000) R16.1@540,3000 ; v1(475,3050) R16.1@540,3050 ; C20.1@525,2541.92 TP11.1@525,2650
  Top Layer w25: v1(250,2650) v1(350,2650) ; v1(250,2775) v1(350,2775)
  Top Layer w35: T1.5@300,2655 C16.2@300,2770
MSP_DM: C3.1 R7.2 U2.52 | length 497
  Top Layer w8: U2.52@211.39,976.78 211.39,965.91 200.7,955.22 200.7,720.25 188,707.54 188,574.56 210,552.56 R7.2@210,548.62 C3.1@260,548.62
MSP_DP: C4.1 R2.1 R6.2 R10.2 U2.50 | length 627.5
  Top Layer w8: R10.2@50,548.62 C4.1@100,548.62 R6.2@150,548.62 150,552.5 170,572.5 170,715 182.7,727.7 182.7,955.22 172.01,965.91 U2.50@172.01,976.78 ; R2.1@100,851.38 181.32,851.38
MSP_PUR: R2.2 R13.1 U2.51 | length 250.3
  Top Layer w8: R13.1@50,898.62 R2.2@100,898.62 ; R2.2@101.38,900 v1(135,900) ; U2.51@191.7,976.78 v1(191.7,1010)
  Bottom Layer w8: v1(135,900) 191.7,956.7 v1(191.7,1010)
MSPV18: C12.1 U2.55 | length 225.7
  Top Layer w10: U2.55@270.46,976.78 270.46,944.26 325,889.72 C12.1@325,773.62
MSPVCORE: C14.1 U2.17 | length 87.5
  Top Layer w10: U2.17@447.67,1323.23 447.67,1342.67 473.62,1368.62 C14.1@473.62,1400
NetD1_2: D1.2 R4.2 | length 67.1
  Top Layer w8: D1.2@482.87,1473.62 R4.2@550,1473.62
NetD2_2: D2.2 R3.2 | length 67.1
  Top Layer w8: D2.2@131.5,1475 R3.2@198.62,1475
NetD3_2: D3.2 J1.1 | length 123
  Top Layer w30: D3.2@425,328.35 425,285 437.8,272.2 J1.1@437.8,210.63
NetD5_2: D5.2 T1.6 | length 148
  Top Layer w35: D5.2@75,2710.53 144.47,2710.53 T1.6@200,2655
NetD7_2: D7.2 T1.4 | length 148
  Top Layer w35: T1.4@400,2655 455.53,2710.53 D7.2@525,2710.53
NetJ1_5: J1.5 J1.6 R11.2 | length 696.3
  Top Layer w20: R11.2@75,293.5 75,250 69.68,244.68 J1.6@69.68,108.27 141.73,108.27 200,50 400,50 458.27,108.27 J1.5@530.32,108.27
NetQ1_1: Q1.1 R1.2 R5.2 | length 133.5
  Top Layer w10: Q1.1@462.6,1877.76 462.6,1842.4 476.38,1828.62 R1.2@476.38,1800 R5.2@476.38,1750
NetQ2_1: Q2.1 R8.2 R9.2 | length 133.5
  Top Layer w10: Q2.1@62.6,1877.76 62.6,1842.4 76.38,1828.62 R9.2@76.38,1800 R8.2@76.38,1750
NetQ2_3: Q2.3 R5.1 | length 536.4
  Top Layer w10: Q2.3@100,1972.24 102.24,1970 135,1970 230,1875 305,1875 455,1725 498.62,1725 R5.1@523.62,1750
NetQ3_1: Q3.1 R18.1 | length 58.5
  Top Layer w10: R18.1@323.62,1975 323.62,1946.38 337.4,1932.6 Q3.1@337.4,1922.24
NetQ4_1: Q4.1 R22.1 | length 72.4
  Top Layer w10: R22.1@400,3176.37 418.63,3176.37 442.24,3152.76 Q4.1@462.6,3152.76
NetQ4_3: Q4.3 R17.1 | length 51.4
  Top Layer w15: Q4.3@500,3247.24 R17.1@500,3298.62
NetQ5_1: Q5.1 R17.2 R20.1 | length 593.4
  Top Layer w15: R20.1@75,3023.62 98.62,3023.62 112.4,3037.4 Q5.1@152.76,3037.4 206.4,3037.4 259,3090 365,3090 v1(400,3125) ; v1(400,3300) R17.2@451.38,3300
  Bottom Layer w15: v1(400,3125) v1(400,3300)
NetQ5_3: Q5.3 R16.2 | length 61.6
  Top Layer w25: Q5.3@247.25,3000 R16.2@308.86,3000
NetR13_2: R13.2 S1.1 | length 66.4
  Top Layer w8: S1.1@50,785 R13.2@50,851.38
NetT1_1: T1.1 U3.3 | length 135.4
  Top Layer w25: T1.1@200,2295 200,2235 230.87,2204.13 U3.3@262.6,2204.13
NetT1_3: T1.3 U3.1 | length 135.4
  Top Layer w25: U3.1@337.4,2204.13 369.13,2204.13 400,2235 T1.3@400,2295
